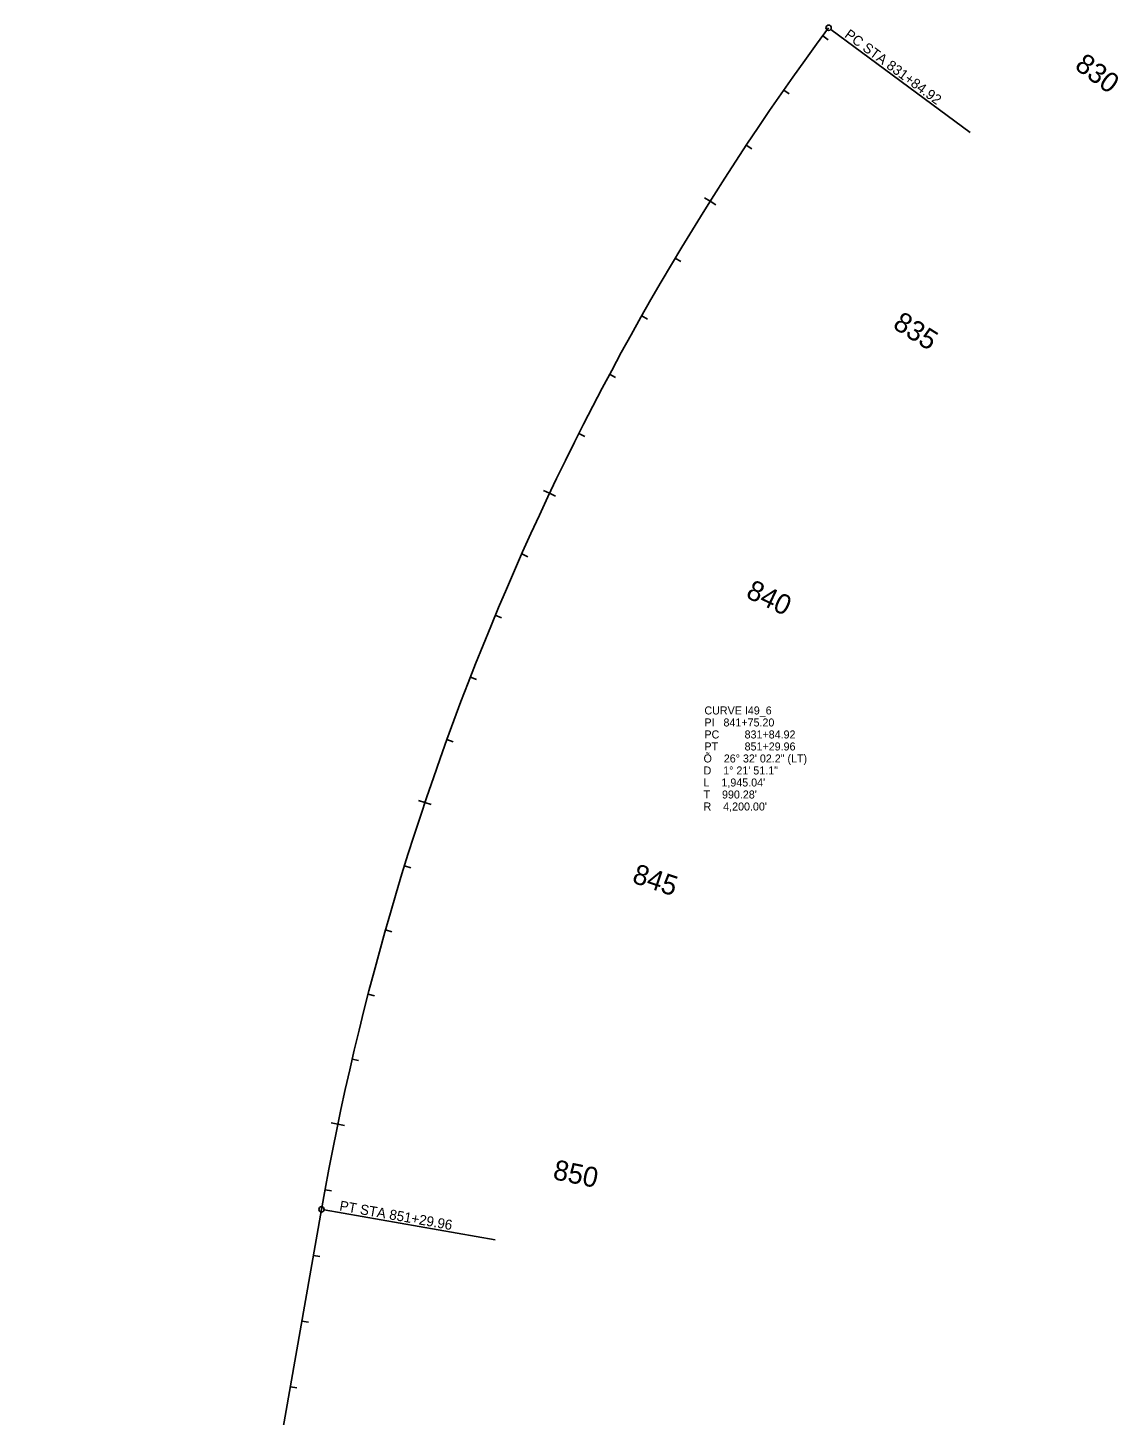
# Model space of a CAD drawing. Extents: x 2819977 to 2827606, y 116785 to 150320.
# Drawn here: x 2821007 to 2822642, y 134009 to 136089 of the extents above; entities that cross this region are included whole.
import ezdxf

# ---------------------------------------------------------------- set-up
doc = ezdxf.new("R2010")
doc.units = 0
for name, color, linetype in [('Default', 7, 'Continuous'), ('Modeling-Flow Arrows-Existing', 7, 'Continuous'), ('Modeling-Spot-Existing', 7, 'Continuous'), ('Modeling-Triangle Verticies-Existing', 7, 'Continuous')]:
    doc.layers.add(name, color=color, linetype=linetype)

msp = doc.modelspace()

# ---------------------------------------------------------------- linework, layer by layer
at = {"layer": 'Default'}
msp.add_line((2821447.5, 134317.2), (2821007.1, 131809.7), dxfattribs=at)
msp.add_arc((2825584.2, 133590.7), 4200, 143.5041, 170.0381, dxfattribs=at)
at = {"layer": 'Modeling-Flow Arrows-Existing'}
for p, q in [((2822198.9, 136076.5), (2822206.9, 136070.6)), ((2822140.6, 135995.2), (2822148.8, 135989.5)), ((2822084.4, 135912.6), (2822092.7, 135907.1)), ((2822030.1, 135828.6), (2822021.6, 135833.9)), ((2822030.1, 135828.6), (2822038.5, 135823.3)), ((2821977.8, 135743.4), (2821986.4, 135738.2)), ((2821927.6, 135656.9), (2821936.3, 135652)), ((2821879.4, 135569.3), (2821888.3, 135564.5)), ((2821833.4, 135480.5), (2821842.3, 135476)), ((2821789.5, 135390.7), (2821780.4, 135394.9)), ((2821789.5, 135390.7), (2821798.5, 135386.4)), ((2821747.7, 135299.8), (2821756.8, 135295.7)), ((2821708.1, 135208), (2821717.3, 135204.1)), ((2821670.7, 135115.2), (2821680, 135111.6)), ((2821635.5, 135021.6), (2821644.9, 135018.2)), ((2821602.5, 134927.2), (2821593.1, 134930.4)), ((2821602.5, 134927.2), (2821612, 134924)), ((2821571.8, 134832.1), (2821581.4, 134829.1)), ((2821543.4, 134736.2), (2821553, 134733.5)), ((2821517.3, 134639.7), (2821527, 134637.2)), ((2821493.5, 134542.5), (2821503.2, 134540.3)), ((2821472, 134444.9), (2821462.2, 134446.9)), ((2821472, 134444.9), (2821481.8, 134442.8)), ((2821452.8, 134346.7), (2821462.6, 134344.9)), ((2821447.5, 134317.2), (2821007.1, 131809.7)), ((2821435.4, 134248.3), (2821445.2, 134246.5)), ((2821418.1, 134149.8), (2821427.9, 134148)), ((2821400.8, 134051.3), (2821410.6, 134049.6))]:
    msp.add_line(p, q, dxfattribs=at)
msp.add_arc((2825584.2, 133590.7), 4200, 143.5041, 170.0381, dxfattribs=at)
at = {"layer": 'Modeling-Spot-Existing'}
for p, q in [((2822211, 136086.3), (2822419.8, 135931.8)), ((2821451.5, 134316.6), (2821708, 134271.5))]:
    msp.add_line(p, q, dxfattribs=at)
for centre in [(2822207.8, 136088.7), (2821447.5, 134317.2)]:
    msp.add_circle(centre, 4, dxfattribs=at)

# ---------------------------------------------------------------- texts
at = {"layer": 'Modeling-Flow Arrows-Existing'}
for s, rotation, p in [(' 830', 323.5041, (2822566.1, 136035)), (' 835', 327.8024, (2822292.9, 135645.4)), (' 840', 334.6233, (2822072.1, 135240)), (' 845', 341.4442, (2821901.1, 134811.2)), (' 850', 348.2651, (2821782.2, 134365.1))]:
    msp.add_text(s, height=30, rotation=rotation, dxfattribs=at).set_placement(p)
at = {"layer": 'Modeling-Spot-Existing'}
for s, rotation, p in [('PC STA 831+84.92', 323.5041, (2822230.5, 136075.6)), ('PT STA 851+29.96', 350.0381, (2821473.6, 134315.7))]:
    msp.add_text(s, height=15, rotation=rotation, dxfattribs=at).set_placement(p)
at = {"layer": 'Modeling-Triangle Verticies-Existing'}
for s, p in [('CURVE I49_6', (2822021.6, 135059.2)), ('PI   841+75.20', (2822021.6, 135041.2)), ('PC', (2822021.6, 135023.2)), ('831+84.92', (2822081.8, 135023.2)), ('Õ    26%%d 32\' 02.2" (LT)', (2822020.3, 134987.2)), ('PT', (2822021.6, 135005.2)), ('851+29.96', (2822081.8, 135005.2)), ('D    1%%d 21\' 51.1"', (2822020.3, 134969.2)), ("L    1,945.04'", (2822020.3, 134951.2)), ("T    990.28'", (2822020.3, 134933.2)), ("R    4,200.00'", (2822020.3, 134915.2))]:
    msp.add_text(s, height=12, dxfattribs=at).set_placement(p)

doc.saveas('drawing.dxf')
